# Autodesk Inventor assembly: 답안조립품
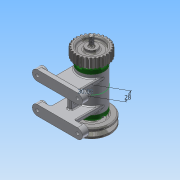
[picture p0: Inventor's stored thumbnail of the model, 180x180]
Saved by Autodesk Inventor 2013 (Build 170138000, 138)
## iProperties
Created: 2015-11
Part Number: 답안조립품
Document SubType Name: Assembly
Designer: user-11
Author: user-11
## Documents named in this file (13)
- C:\Users\user-11\Desktop\451109V1028\답안조립품.iam
- C:\Users\user-11\Desktop\451109V1028\1-본체.ipt
- C:\Users\user-11\Desktop\451109V1028\커버.ipt
- C:\Users\user-11\Desktop\451109V1028\베어링 15 x 32 x 9.ipt
- C:\Users\user-11\Desktop\451109V1028\축.ipt
- C:\Users\user-11\Desktop\451109V1028\키 3 x 3 x 12.ipt
- C:\Users\user-11\Desktop\451109V1028\오일 실 15 25 7.ipt
- C:\Users\user-11\Desktop\451109V1028\V벨트풀리.ipt
- C:\Users\user-11\Desktop\451109V1028\스퍼기어.ipt
- C:\Users\user-11\Desktop\451109V1028\볼트 M4 x 12.ipt
- C:\Users\user-11\Desktop\451109V1028\와셔 8x17.ipt
- C:\Users\user-11\Desktop\451109V1028\스프링와셔 8.ipt
- C:\Users\user-11\Desktop\451109V1028\너트 M 8.ipt
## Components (12 placed, 4 different names)
1. 1-본체:1
2. KS B 2023 6002 - 15 x 32 x 9:1
3. KS B 2023 6002 - 15 x 32 x 9:2
4. V벨트풀리:1 — 각도:3
5. ISO 4762 M4 x 12:5
6. ISO 4762 M4 x 12:6
7. ISO 4762 M4 x 12:7
8. ISO 4762 M4 x 12:8
9. ISO 4762 M4 x 12:1
10. ISO 4762 M4 x 12:2
11. ISO 4762 M4 x 12:3
12. ISO 4762 M4 x 12:4
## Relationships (1: Angle 1)
- 각도:3 [Angle]: V벨트풀리:1
